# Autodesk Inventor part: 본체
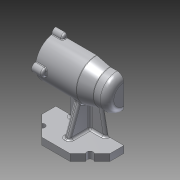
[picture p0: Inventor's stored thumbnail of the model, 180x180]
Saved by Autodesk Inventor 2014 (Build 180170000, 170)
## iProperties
Created: 2021-01
Part Number: 본체
Material: Aluminum 6061
Document SubType Name: Modeling
Designer: kh
Density: 2.71 g/cm^3
Appearance: Aluminum - Flat
Mass: 632.165 g
Surface Area: 614.058 cm^2
Volume: 233.271 cm^3
Author: kh
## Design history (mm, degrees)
sketch "Sketch1" dims "d0" = 100
  geometry: L1 (0, 0)-(0, 50); L2 (20.711, 50)-(50, 20.711); L3 (50, 20.711)-(50, -20.711); L4 (50, -20.711)-(20.711, -50); L5 (20.711, -50)-(-20.711, -50); L6 (-20.711, -50)-(-50, -20.711); L7 (-50, -20.711)-(-50, 20.711); L8 (-50, 20.711)-(-20.711, 50); L9 (-20.711, 50)-(20.711, 50); L10 (0, 0)-(-35.355, 35.355); 2 further points
  constraints: 20 end point, 3 coincident, 2 midpoint, 1 perpendicular, 1 vertical, 1 vertical alignment, 19 other
extrude "Extrusion1" new body sketch "Sketch1" distance "d1" = 10; taper "d2" = 0 deg
sketch "Sketch2"
  geometry: 2 further points
hole "Hole1" sketch "Sketch2" at (-35.355, 35.355) diameter "d3" = 9; stored, may be unused: countersink angle "d7" = 90 deg, drill point angle "d9" = 118 deg; dims "d4" = 6, "d5" = 4, "d6" = 2, "d8" = 8
pattern_circular "Circular Pattern1" dims angle "d11" = 360 deg
sketch "Sketch3"
  geometry: L1 (-50, 75)-(50, 75); L2 (50, 75)-(50, 105); L3 (50, 105)-(-10, 105); L4 (-10, 105)-(-30, 100); L5 (-30, 100)-(-50, 100); L6 (-50, 100)-(-50, 75); L7 (50, 0)-(50, 10) reference; L8 (50, 96)-(35, 96); L9 (35, 96)-(35, 99); L10 (35, 99)-(-7, 99); L11 (-7, 99)-(-7, 96); L12 (-7, 96)-(-19, 96); L13 (-19, 96)-(-19, 92.5); L14 (-19, 92.5)-(-37, 92.5); L15 (-37, 92.5)-(-37, 91); L16 (-37, 91)-(-41, 91); L17 (-41, 91)-(-41, 85.5); L18 (-41, 85.5)-(-44, 85.5); L19 (-44, 85.5)-(-44, 75); L20 (-44, 75)-(50, 75); L21 (50, 96)-(50, 75); 3 further points
  constraints: 40 end point, 10 parallel, 6 perpendicular, 2 collinear, 2 midpoint, 2 point on line, 1 horizontal, 1 vertical alignment
  dimensions: "d13" = 60 diameter of L3 L1; "d14" = 50 diameter of L5 L1; "d15" = 75 vertical distance of point (0, 0) L1.start; "d16" = 20 distance of L4.end L5.end; "d17" = 100 distance between parallel lines of L6 L2; "d18" = 40 horizontal distance of L5.end L3.end; "d19" = 42 diameter of L8 L20; "d20" = 48 diameter of L10 L1; "d21" = 42 diameter of L12 L1; "d22" = 35 diameter of L14 L20; "d23" = 32 diameter of L16 L20; "d24" = 21 diameter of L18 L1; "d25" = 15 distance of L8.start L8.end; "d26" = 42 distance of L9.end L10.end; "d27" = 12 distance of L11.end L12.end; "d28" = 3 distance of L17.end L18.end; "d29" = 4 distance of L15.end L16.end; "d30" = 18 distance of L13.end L14.end
revolve "Revolution1" sketch "Sketch3" stored, may be unused: angle "d31" = 90 deg
sketch "Sketch4"
  geometry: L1 (0, -4)-(-27, -4); L2 (-27, -4)-(-27, 4); L3 (-27, 4)-(0, 4); L4 (0, 4)-(0, -4); L5 (-50, -20.711)-(-50, 20.711) reference; 2 further points
  constraints: 8 end point, 2 parallel, 1 coincident, 1 horizontal, 1 midpoint, 1 perpendicular
  dimensions: "d32" = 8 distance of L1.end L2.end; "d33" = 23 distance between parallel lines of L2 L5
extrude "Extrusion2" join sketch "Sketch4" stored distance "d34" = 10; taper "d35" = 0 deg
sketch "Sketch5"
  geometry: L1 (-20.711, 10)-(-32.173, 10) reference; L2 (-38.537, 10)-(-30.855, 10) reference; L3 (-38.537, 10)-(-50, 10) reference; L4 (20.711, 10)-(-20.711, 10) reference; L5 (-27, 10)-(-20.233, 44.813); 1 further point
  constraints: 2 end point, 1 point on line
  dimensions: "d36" = 23 distance of L5.start L3.end; "d37" = 101 deg angle of L1 L5
feature "Rib1" sketch "Sketch5" dims "d38" = 1, "d39" = 8, "d40" = 0, "d41" = 0, "d42" = 1, "d43" = 1
sketch "Sketch6"
  geometry: L1 (-50, 10)-(-38.537, 10) reference; L2 (-35, 10)-(-21.146, 48.062); 1 further point
  constraints: 2 end point, 1 point on line
  dimensions: "d44" = 15 distance of L1.start L2.start; "d45" = 110 deg angle of L2 L1
feature "Rib2" sketch "Sketch6" dims "d46" = 1, "d47" = 8, "d48" = 0, "d49" = 0, "d50" = 1, "d51" = 1
mirror "Mirror1"
sketch "Sketch7"
  geometry: L1 (0, 0)-(30, 0); C1 r 6 at (30, 0); 1 further point
  constraints: 2 end point, 1 centre point, 1 coincident, 1 horizontal, 1 horizontal alignment, 1 other
  dimensions: "d52" = 12 diameter of C1
extrude "Extrusion3" join sketch "Sketch7" distance "d53" = 16; taper "d54" = 0 deg
fillet "Fillet1" dims "d55" = 3
fillet "Fillet2" dims "d56" = 1
pattern_circular "Circular Pattern2" dims "d58" = 360 deg
hole "Hole2" diameter "d62" = 3.459; stored, may be unused: countersink angle "d66" = 90 deg, drill point angle "d68" = 118 deg; dims "d60" = 10, "d61" = 10, "d63" = 8, "d64" = 4, "d65" = 2, "d67" = 10
pattern_circular "Circular Pattern3" dims angle "d70" = 360 deg
fillet "Fillet3" dims "d72" = 0.3, "d73" = 3
chamfer "Chamfer1" distance "d74" = 1; stored, may be unused: second distance "d75" = 2, angle "d76" = 45 deg
fillet "Fillet4" dims "d77" = 10
fillet "Fillet5" dims "d78" = 3
fillet "Fillet6" dims "d79" = 3
fillet "Fillet7" dims "d80" = 3
workplane "Work Plane1"
sketch "Sketch9"
  geometry: L1 (30, 6.771)-(30, 29.226) reference; L2 (30, 5.998)-(30, -5.998) reference; L3 (30, 0)-(-34.43, 0); 2 further points
  constraints: 2 end point, 1 midpoint, 1 perpendicular, 1 point on line, 1 other
  dimensions: "d81" = 38 distance from line of point (-8, 0) L1
emboss "Emboss1" sketch "Sketch9" dims "d82" = 0.5, "d83" = 0
body "Solid1"
